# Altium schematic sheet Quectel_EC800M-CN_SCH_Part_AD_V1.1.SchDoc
size 594 x 419 mm; Organization: Altium Limited; Address1: L3, 12a Rodborough Rd; Address2: Frenchs Forest; Address3: NSW; Address4: Australia 2086
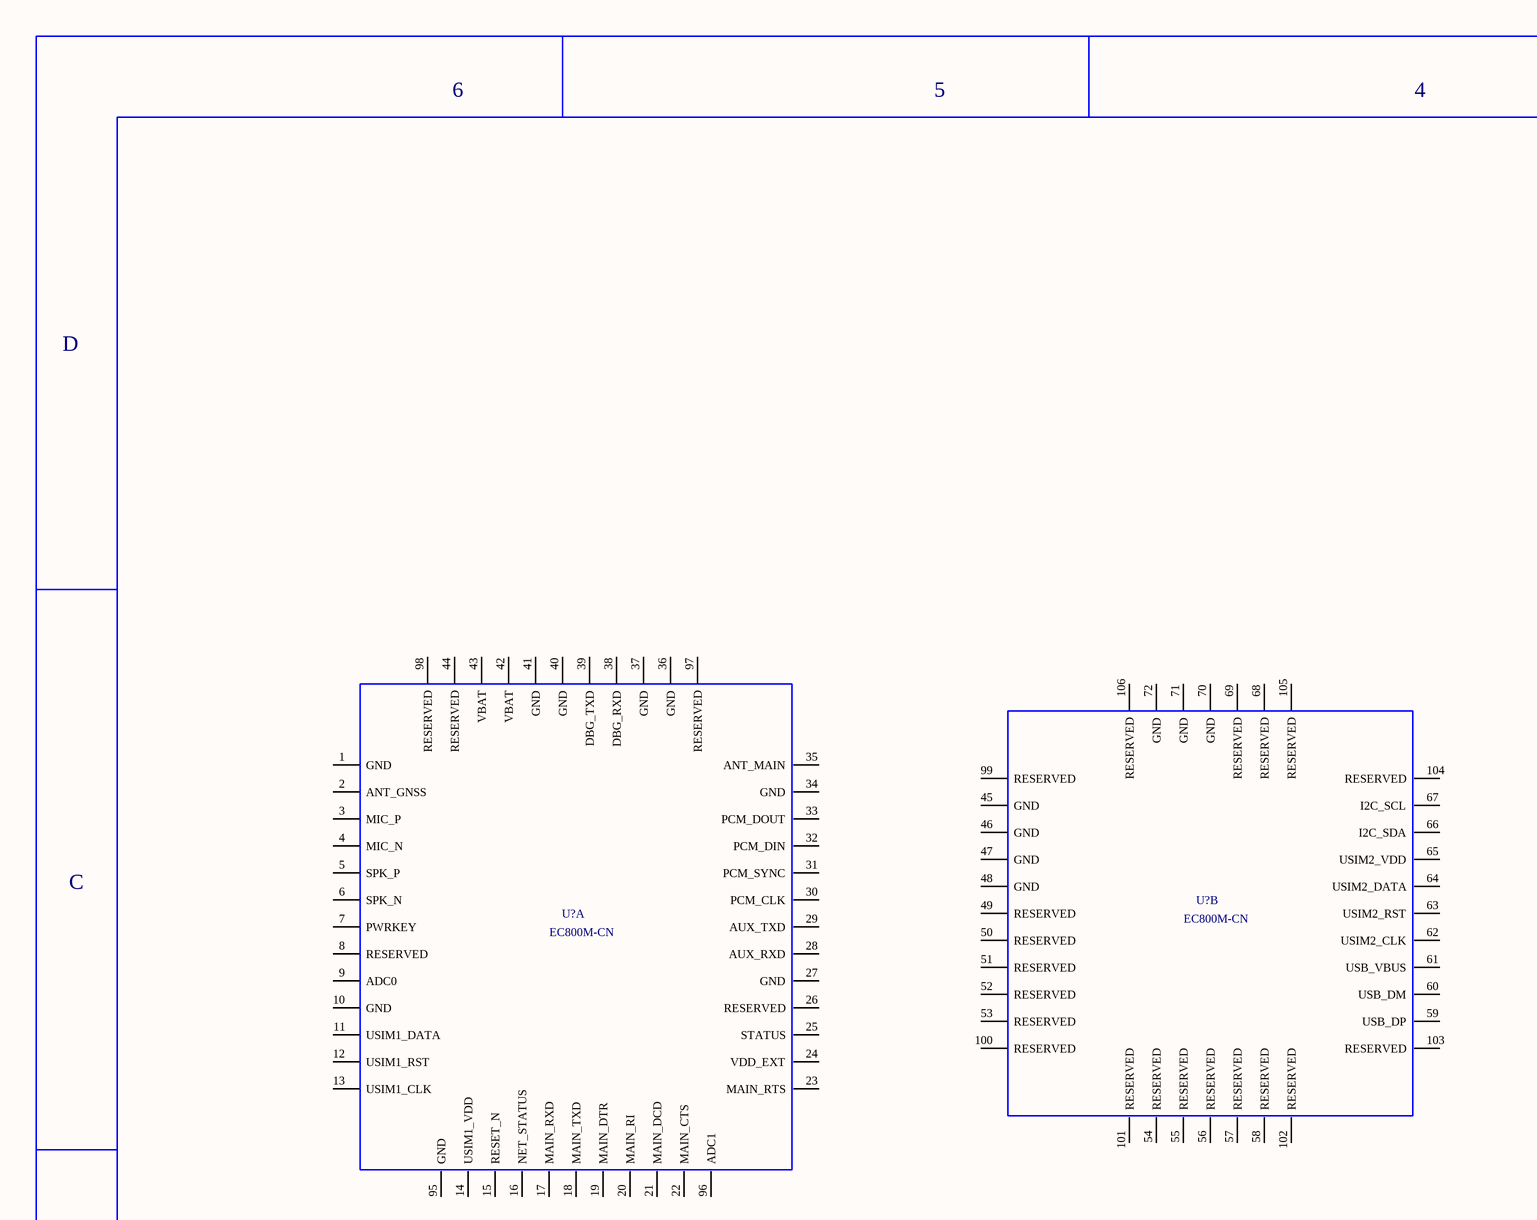
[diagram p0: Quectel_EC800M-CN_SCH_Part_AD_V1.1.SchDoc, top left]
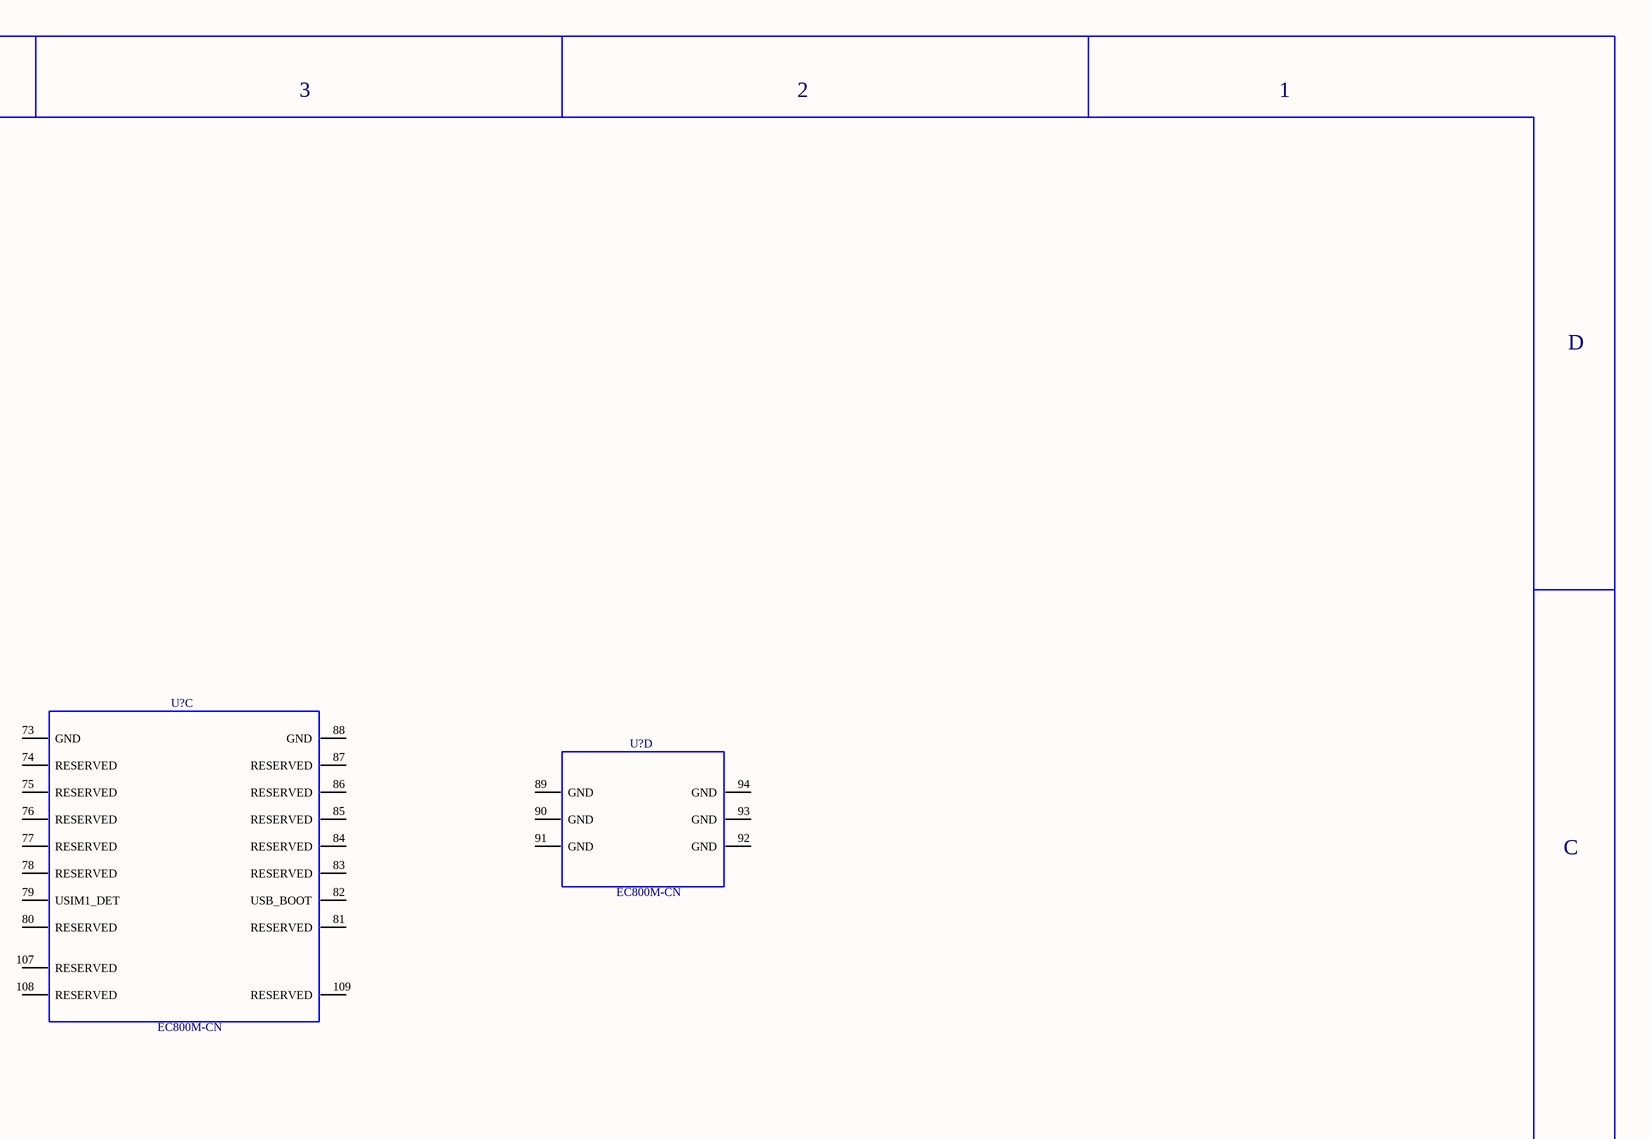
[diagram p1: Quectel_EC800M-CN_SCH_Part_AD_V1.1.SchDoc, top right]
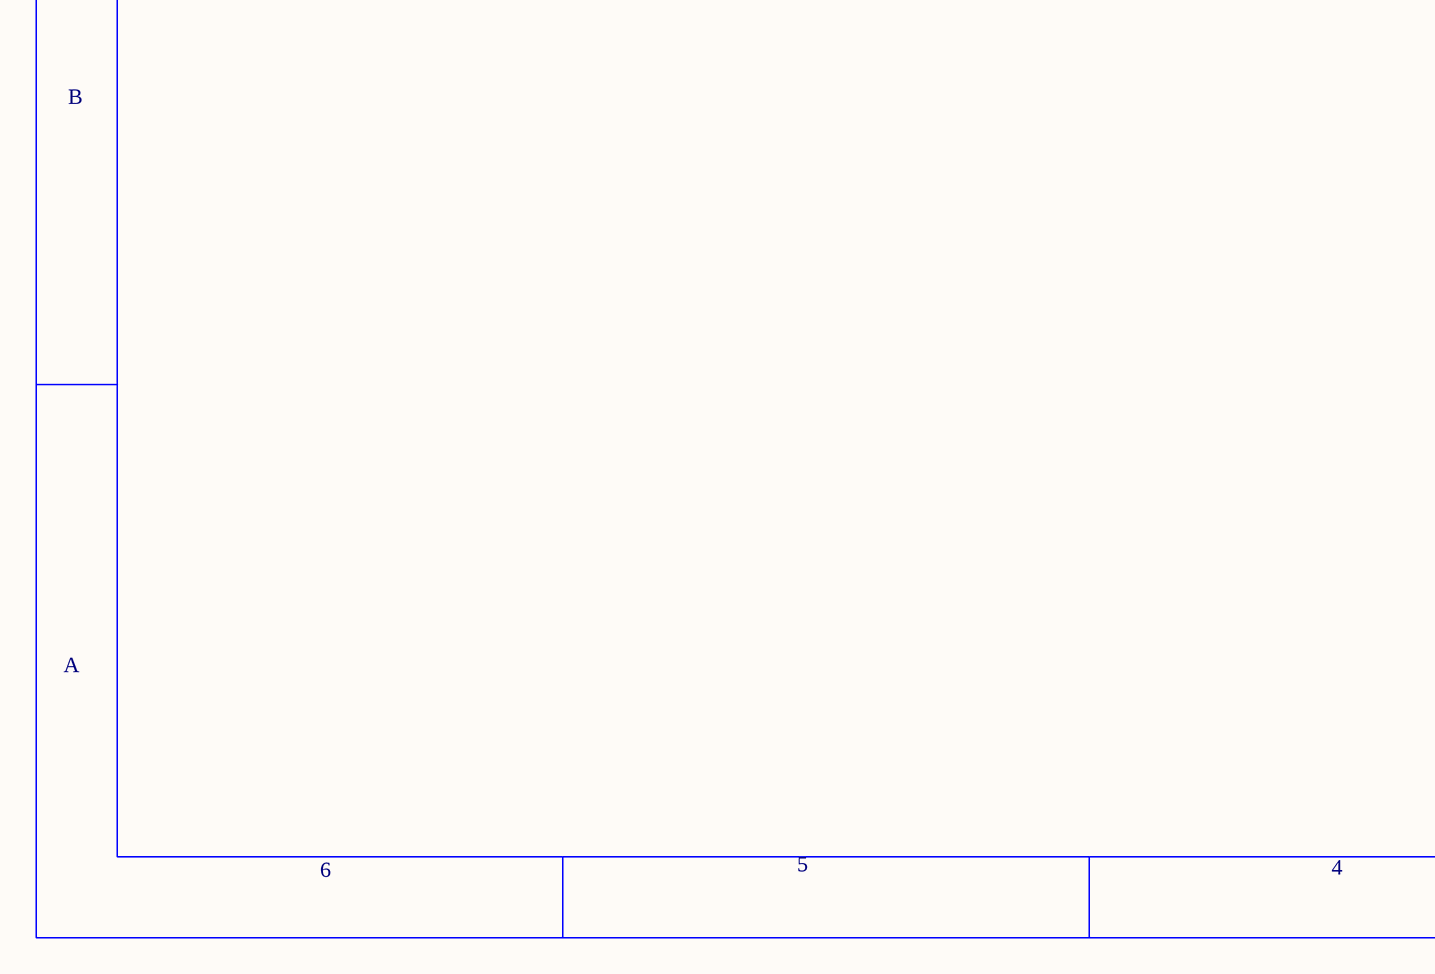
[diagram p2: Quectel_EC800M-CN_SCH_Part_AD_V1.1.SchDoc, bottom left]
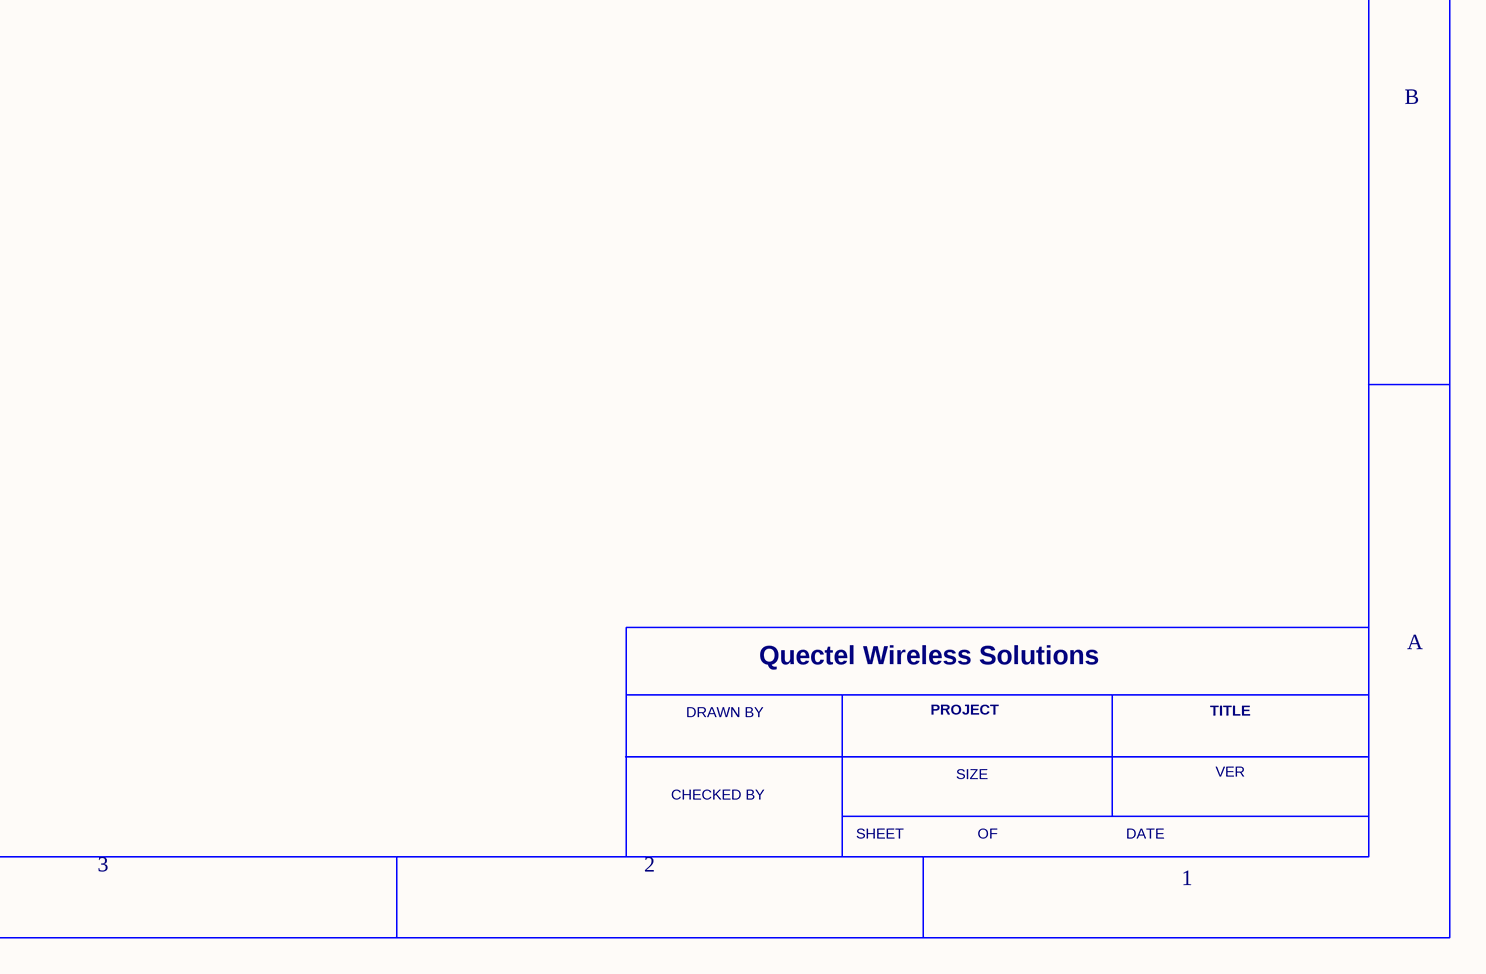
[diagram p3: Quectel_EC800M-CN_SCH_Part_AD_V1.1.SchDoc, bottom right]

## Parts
(Parts that share a designator on the sheet are numbered #1, #2 ... from top to bottom, then left to right.)
U?#1  EC800M-CN  (part D of 4)
U?#2  EC800M-CN  (part C of 4)
U?#3  EC800M-CN  (part B of 4)
U?#4  EC800M-CN  (part A of 4)

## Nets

Not connected (* = marked no-connect by the designer): U?#1 89(GND) 90(GND) 91(GND) 92(GND) 93(GND) 94(GND); U?#2 73(GND) 74(RESERVED) 75(RESERVED) 76(RESERVED) 77(RESERVED) 78(RESERVED) 79(USIM1_DET) 80(RESERVED) 81(RESERVED) 82(USB_BOOT) 83(RESERVED) 84(RESERVED) 85(RESERVED) 86(RESERVED) 87(RESERVED) 88(GND) 107(RESERVED) 108(RESERVED) 109(RESERVED); U?#3 45(GND) 46(GND) 47(GND) 48(GND) 49(RESERVED) 50(RESERVED) 51(RESERVED) 52(RESERVED) 53(RESERVED) 54(RESERVED) 55(RESERVED) 56(RESERVED) 57(RESERVED) 58(RESERVED) 59(USB_DP) 60(USB_DM) 61(USB_VBUS) 62(USIM2_CLK) 63(USIM2_RST) 64(USIM2_DATA) 65(USIM2_VDD) 66(I2C_SDA) 67(I2C_SCL) 68(RESERVED) 69(RESERVED) 70(GND) 71(GND) 72(GND) 99(RESERVED) 100(RESERVED) 101(RESERVED) 102(RESERVED) 103(RESERVED) 104(RESERVED) 105(RESERVED) 106(RESERVED); U?#4 1(GND) 2(ANT_GNSS) 3(MIC_P) 4(MIC_N) 5(SPK_P) 6(SPK_N) 7(PWRKEY) 8(RESERVED) 9(ADC0) 10(GND) 11(USIM1_DATA) 12(USIM1_RST) 13(USIM1_CLK) 14(USIM1_VDD) 15(RESET_N) 16(NET_STATUS) 17(MAIN_RXD) 18(MAIN_TXD) 19(MAIN_DTR) 20(MAIN_RI) 21(MAIN_DCD) 22(MAIN_CTS) 23(MAIN_RTS) 24(VDD_EXT) 25(STATUS) 26(RESERVED) 27(GND) 28(AUX_RXD) 29(AUX_TXD) 30(PCM_CLK) 31(PCM_SYNC) 32(PCM_DIN) 33(PCM_DOUT) 34(GND) 35(ANT_MAIN) 36(GND) 37(GND) 38(DBG_RXD) 39(DBG_TXD) 40(GND) 41(GND) 42(VBAT) 43(VBAT) 44(RESERVED) 95(GND) 96(ADC1) 97(RESERVED) 98(RESERVED)

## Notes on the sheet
- 6
- 5
- 4
- 3
- 2
- 1
- D
- C
- B
- A
- Quectel Wireless Solutions
- DRAWN BY
- PROJECT
- TITLE
- CHECKED BY
- SIZE
- VER
- SHEET
- OF
- DATE

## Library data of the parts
U?#1-U?#4 = EC800M-CN: EC800M-CN Moudle 109PIN 15.8X17.7mm H2.4mm RO; Manufacturer: Quectel; Geometry_Height: 2.4mm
